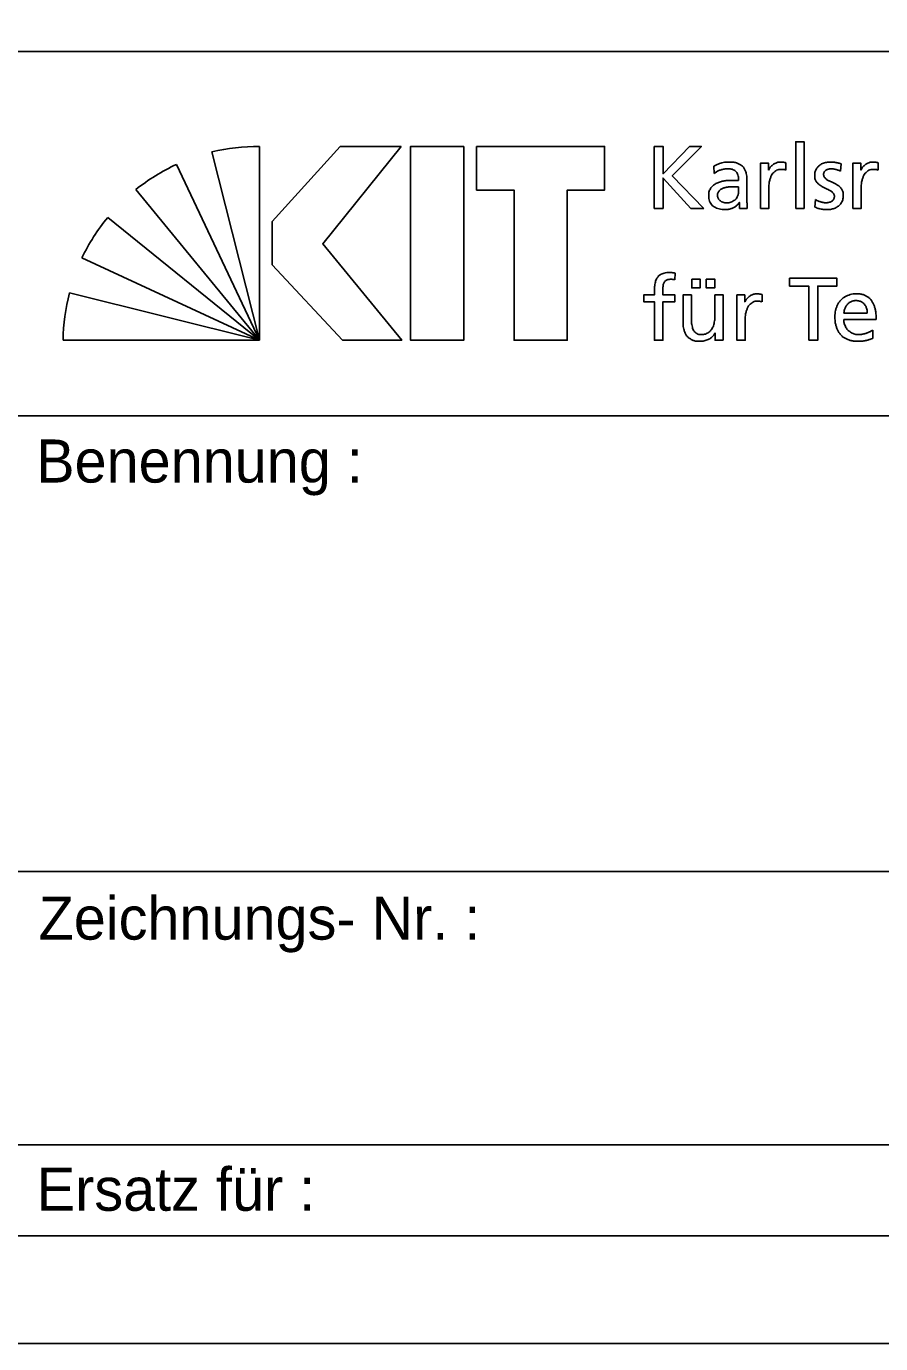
# Model space of a CAD drawing. Extents: x 0 to 11.9, y 0 to 8.4.
# Drawn here: x 11.007 to 11.403, y 0 to 0.612 of the extents above; entities that cross this region are included whole.
import ezdxf

# ---------------------------------------------------------------- set-up
doc = ezdxf.new("R2010")
doc.units = 0
doc.layers.add('90_Plankopf', color=7, linetype='Continuous')

msp = doc.modelspace()

# ---------------------------------------------------------------- linework, layer by layer
at = {"layer": '90_Plankopf'}
for p, q in [((10.0612, 0.5999), (11.84, 0.5999)), ((10.0612, 0.5999), (11.84, 0.5999)), ((11.09275, 0.55333), (11.11481, 0.46586)), ((11.11481, 0.46586), (11.11481, 0.55584)), ((11.2981, 0.55586), (11.2981, 0.52706)), ((11.11481, 0.46586), (11.07633, 0.54752)), ((11.32579, 0.54662), (11.326, 0.54332)), ((11.35926, 0.54484), (11.35926, 0.54831)), ((11.38457, 0.54439), (11.3849, 0.54778)), ((11.40211, 0.54484), (11.40211, 0.54831)), ((11.34118, 0.53118), (11.34118, 0.53989)), ((11.05744, 0.53585), (11.11481, 0.46586)), ((11.3373, 0.53709), (11.3373, 0.53523)), ((11.2981, 0.52706), (11.30222, 0.52706)), ((11.31506, 0.52706), (11.32108, 0.52706)), ((11.37297, 0.53118), (11.37277, 0.52772)), ((11.11481, 0.46586), (11.04434, 0.52286)), ((11.0324, 0.50413), (11.11481, 0.46586)), ((11.30773, 0.49393), (11.3079, 0.49706)), ((11.11481, 0.46586), (11.02658, 0.48788)), ((11.34827, 0.48365), (11.34827, 0.48712)), ((11.39706, 0.47841), (11.38616, 0.47841)), ((11.38616, 0.47552), (11.40119, 0.47552)), ((11.02364, 0.46586), (11.11481, 0.46586)), ((11.39958, 0.46673), (11.39958, 0.47061)), ((11.00001, 0.4307), (11.84, 0.4307)), ((11.00001, 0.2192), (11.84, 0.2192)), ((11.00001, 0.0923), (11.84, 0.0923)), ((11.84, 0.05), (10.0612, 0.05)), ((10.178, 0.05), (11.84, 0.05)), ((10.178, 0.05), (11.84, 0.05))]:
    msp.add_line(p, q, dxfattribs=at)
for points in [[(0, 0), (11.89, 0), (11.89, 8.41), (0, 8.41)], [(0.25, 0.05), (11.84, 0.05), (11.84, 8.36), (0.25, 8.36)], [(11.18066, 0.55586), (11.15236, 0.55586), (11.12073, 0.52099), (11.12073, 0.50092), (11.15338, 0.46586), (11.18085, 0.46586), (11.14422, 0.51063)], [(11.2097, 0.55586), (11.2097, 0.46586), (11.18501, 0.46586), (11.18501, 0.55586)], [(11.21562, 0.55586), (11.21562, 0.5356), (11.23301, 0.5356), (11.23301, 0.46586), (11.25771, 0.46586), (11.25771, 0.5356), (11.2751, 0.5356), (11.2751, 0.55586)]]:
    msp.add_lwpolyline(points, close=True, dxfattribs=at)
for points in [[(11.36381, 0.52706), (11.36768, 0.52706), (11.36768, 0.55801), (11.36381, 0.55801), (11.36381, 0.52706)], [(11.32108, 0.52706), (11.30647, 0.54224), (11.32001, 0.55586), (11.31452, 0.55586), (11.30222, 0.54319), (11.30222, 0.55586), (11.2981, 0.55586)], [(11.35122, 0.54484), (11.35113, 0.54484), (11.35113, 0.5481), (11.3475, 0.5481), (11.3475, 0.52706), (11.35138, 0.52706), (11.35138, 0.53663)], [(11.39407, 0.54484), (11.39398, 0.54484), (11.39398, 0.5481), (11.39035, 0.5481), (11.39035, 0.52706), (11.39423, 0.52706), (11.39423, 0.53663)], [(11.30222, 0.52706), (11.30222, 0.54117), (11.31506, 0.52706)], [(11.33763, 0.52978), (11.33772, 0.52978), (11.33772, 0.52706), (11.34135, 0.52706)], [(11.31554, 0.49426), (11.31554, 0.49013), (11.31942, 0.49013), (11.31942, 0.49426), (11.31554, 0.49426)], [(11.32231, 0.49426), (11.32231, 0.49013), (11.32619, 0.49013), (11.32619, 0.49426), (11.32231, 0.49426)], [(11.3699, 0.46586), (11.37403, 0.46586), (11.37403, 0.49104), (11.38298, 0.49104), (11.38298, 0.49467), (11.36094, 0.49467), (11.36094, 0.49104), (11.3699, 0.49104), (11.3699, 0.46586)], [(11.29824, 0.48885), (11.29824, 0.48691), (11.29329, 0.48691), (11.29329, 0.48378), (11.29824, 0.48378), (11.29824, 0.46586), (11.30212, 0.46586), (11.30212, 0.48378), (11.30769, 0.48378), (11.30769, 0.48691), (11.30212, 0.48691), (11.30212, 0.48918)], [(11.31542, 0.47602), (11.31542, 0.48691), (11.31154, 0.48691), (11.31154, 0.47441)], [(11.33015, 0.46586), (11.33015, 0.48691), (11.32627, 0.48691), (11.32627, 0.47717)], [(11.34022, 0.48365), (11.34014, 0.48365), (11.34014, 0.48691), (11.33651, 0.48691), (11.33651, 0.46586), (11.34039, 0.46586), (11.34039, 0.47544)], [(11.32631, 0.46921), (11.32639, 0.46921), (11.32639, 0.46586), (11.33015, 0.46586)]]:
    msp.add_lwpolyline(points, dxfattribs=at)
for centre, start, end in [((11.11449, 0.46056), 89.80527, 103.18947), ((11.11662, 0.46118), 115.01261, 128.3968), ((11.11816, 0.46263), 140.78977, 154.17397), ((11.11891, 0.46438), 165.72225, 179.10644)]:
    msp.add_arc(centre, 0.09528, start, end, dxfattribs=at)
for points in [[(11.34118, 0.53989), (11.34119, 0.5418), (11.34091, 0.54341), (11.34033, 0.5447), (11.33975, 0.54599), (11.33884, 0.54696), (11.33759, 0.54762), (11.33635, 0.54827), (11.33472, 0.5486), (11.33272, 0.5486), (11.33138, 0.54859), (11.33014, 0.54841), (11.32898, 0.54804), (11.32782, 0.54768), (11.32676, 0.54721), (11.32579, 0.54662)], [(11.326, 0.54332), (11.32653, 0.54376), (11.32713, 0.54414), (11.32779, 0.54446), (11.32846, 0.54478), (11.32916, 0.54503), (11.3299, 0.5452), (11.33063, 0.54538), (11.33137, 0.54546), (11.3321, 0.54546), (11.33339, 0.54546), (11.33441, 0.54526), (11.33518, 0.54485), (11.33594, 0.54444), (11.33649, 0.54383), (11.33682, 0.54302), (11.33715, 0.54219), (11.33731, 0.54118), (11.3373, 0.53997)], [(11.35926, 0.54831), (11.35899, 0.54837), (11.35873, 0.54841), (11.35849, 0.54846), (11.35824, 0.5485), (11.35798, 0.54854), (11.35769, 0.54856), (11.35741, 0.54859), (11.35708, 0.5486), (11.3567, 0.5486), (11.35595, 0.54859), (11.35523, 0.54843), (11.35452, 0.54811), (11.35382, 0.54779), (11.35318, 0.54736), (11.35261, 0.54679), (11.35203, 0.54623), (11.35157, 0.54558), (11.35122, 0.54484)], [(11.35138, 0.53663), (11.35139, 0.5384), (11.35163, 0.53993), (11.3521, 0.54121), (11.35257, 0.54249), (11.35323, 0.54348), (11.35409, 0.54416), (11.35494, 0.54486), (11.35595, 0.54521), (11.35712, 0.54521), (11.35746, 0.54522), (11.3578, 0.54519), (11.35818, 0.54514), (11.35855, 0.54509), (11.35891, 0.54499), (11.35926, 0.54484)], [(11.3849, 0.54778), (11.38414, 0.54801), (11.38337, 0.5482), (11.38259, 0.54836), (11.38181, 0.54851), (11.38097, 0.54859), (11.38007, 0.5486), (11.37903, 0.5486), (11.37805, 0.54847), (11.37716, 0.5482), (11.37625, 0.54794), (11.37547, 0.54753), (11.3748, 0.547), (11.37412, 0.54647), (11.37359, 0.54579), (11.37322, 0.54498), (11.37284, 0.54417), (11.37265, 0.54321), (11.37264, 0.54212), (11.37265, 0.54128), (11.37282, 0.54056), (11.37315, 0.53994), (11.37347, 0.53933), (11.37391, 0.5388), (11.37445, 0.53834), (11.375, 0.5379), (11.37559, 0.5375), (11.37623, 0.53715), (11.37688, 0.5368), (11.37753, 0.53647), (11.37817, 0.53617), (11.37882, 0.53586), (11.37942, 0.53555), (11.37995, 0.53522), (11.3805, 0.5349), (11.38093, 0.53454), (11.38126, 0.53413), (11.38158, 0.53373), (11.38176, 0.53325), (11.38176, 0.53271), (11.38176, 0.53215), (11.38163, 0.53167), (11.38139, 0.53128), (11.38116, 0.5309), (11.38084, 0.53059), (11.38045, 0.53035), (11.38006, 0.53012), (11.37963, 0.52995), (11.37917, 0.52985), (11.37871, 0.52975), (11.37825, 0.5297), (11.3778, 0.5297), (11.37742, 0.5297), (11.37695, 0.52975), (11.37639, 0.52986), (11.37584, 0.52997), (11.37526, 0.53014), (11.37466, 0.53036), (11.37405, 0.53058), (11.3735, 0.53085), (11.37297, 0.53118)], [(11.37277, 0.52772), (11.37366, 0.52726), (11.3746, 0.52694), (11.37558, 0.52678), (11.37656, 0.52662), (11.37755, 0.52655), (11.37854, 0.52656), (11.37949, 0.52656), (11.3804, 0.52669), (11.38127, 0.52695), (11.38215, 0.52722), (11.38293, 0.52762), (11.38363, 0.52816), (11.38431, 0.52869), (11.38487, 0.52938), (11.38527, 0.5302), (11.38568, 0.53103), (11.38588, 0.532), (11.38589, 0.53312), (11.38588, 0.53408), (11.38571, 0.53489), (11.38539, 0.53556), (11.38506, 0.53622), (11.38462, 0.53679), (11.38408, 0.53726), (11.38354, 0.53772), (11.38295, 0.53811), (11.3823, 0.53845), (11.38165, 0.53878), (11.38101, 0.53909), (11.38036, 0.53937), (11.37971, 0.53966), (11.37912, 0.53995), (11.37858, 0.54026), (11.37804, 0.54058), (11.3776, 0.54095), (11.37727, 0.54136), (11.37695, 0.54179), (11.37678, 0.5423), (11.37677, 0.54291), (11.37678, 0.54348), (11.37696, 0.54396), (11.37729, 0.54434), (11.37763, 0.54472), (11.37808, 0.545), (11.37864, 0.54519), (11.3792, 0.54538), (11.37982, 0.54546), (11.38048, 0.54546), (11.38072, 0.54546), (11.38102, 0.54543), (11.38139, 0.54538), (11.38175, 0.54531), (11.38213, 0.54523), (11.38254, 0.54513), (11.38295, 0.54503), (11.38333, 0.54491), (11.38369, 0.54478), (11.38405, 0.54466), (11.38434, 0.54453), (11.38457, 0.54439)], [(11.40211, 0.54831), (11.40184, 0.54837), (11.40158, 0.54841), (11.40134, 0.54846), (11.4011, 0.5485), (11.40083, 0.54854), (11.40054, 0.54856), (11.40026, 0.54859), (11.39993, 0.5486), (11.39955, 0.5486), (11.3988, 0.54859), (11.39808, 0.54843), (11.39737, 0.54811), (11.39667, 0.54779), (11.39603, 0.54736), (11.39546, 0.54679), (11.39488, 0.54623), (11.39442, 0.54558), (11.39407, 0.54484)], [(11.39423, 0.53663), (11.39424, 0.5384), (11.39448, 0.53993), (11.39495, 0.54121), (11.39542, 0.54249), (11.39608, 0.54348), (11.39694, 0.54416), (11.39779, 0.54486), (11.3988, 0.54521), (11.39997, 0.54521), (11.4003, 0.54522), (11.40065, 0.54519), (11.40103, 0.54514), (11.4014, 0.54509), (11.40175, 0.54499), (11.40211, 0.54484)], [(11.3373, 0.53997), (11.3368, 0.54), (11.33633, 0.54002), (11.33589, 0.54003), (11.33546, 0.54004), (11.33502, 0.54005), (11.33459, 0.54006), (11.33415, 0.54006), (11.33368, 0.54006), (11.33318, 0.54006), (11.33237, 0.54006), (11.33151, 0.53999), (11.33063, 0.53984), (11.32973, 0.5397), (11.32886, 0.53947), (11.32801, 0.53914), (11.32715, 0.53881), (11.32638, 0.53838), (11.32569, 0.53785), (11.32499, 0.53731), (11.32444, 0.53665), (11.32403, 0.53588), (11.32362, 0.53509), (11.32341, 0.53418), (11.3234, 0.53312), (11.32341, 0.5316), (11.32374, 0.53035), (11.32439, 0.52939), (11.32504, 0.52842), (11.32594, 0.5277), (11.3271, 0.52724), (11.32825, 0.52679), (11.32959, 0.52656), (11.33111, 0.52656), (11.332, 0.52657), (11.3328, 0.52668), (11.3335, 0.52689), (11.33421, 0.52709), (11.33483, 0.52736), (11.33536, 0.52769), (11.3359, 0.52802), (11.33635, 0.52837), (11.33673, 0.52874), (11.3371, 0.52911), (11.33741, 0.52945), (11.33763, 0.52978)], [(11.3373, 0.53523), (11.3373, 0.53418), (11.33708, 0.53323), (11.33664, 0.5324), (11.3362, 0.53157), (11.33554, 0.53092), (11.33467, 0.53043), (11.3338, 0.52995), (11.33272, 0.5297), (11.33144, 0.5297), (11.331, 0.5297), (11.33054, 0.52978), (11.33008, 0.52992), (11.32963, 0.53007), (11.3292, 0.53028), (11.32882, 0.53057), (11.32843, 0.53087), (11.32812, 0.53123), (11.32789, 0.53165), (11.32765, 0.53207), (11.32753, 0.53257), (11.32752, 0.53312), (11.32754, 0.53386), (11.32772, 0.53448), (11.32808, 0.53497), (11.32844, 0.53546), (11.32891, 0.53586), (11.32949, 0.53615), (11.33007, 0.53645), (11.33069, 0.53667), (11.33135, 0.53682), (11.33201, 0.53696), (11.33265, 0.53706), (11.33326, 0.53711), (11.33387, 0.53715), (11.33439, 0.53717), (11.33483, 0.53717), (11.33524, 0.53717), (11.33565, 0.53715), (11.33607, 0.53713), (11.33648, 0.53711), (11.33689, 0.53709), (11.3373, 0.53709)], [(11.34135, 0.52706), (11.34132, 0.52726), (11.34129, 0.52753), (11.34126, 0.52787), (11.34125, 0.52821), (11.34122, 0.52865), (11.34121, 0.52919), (11.34119, 0.52973), (11.34118, 0.53039), (11.34118, 0.53118)], [(11.3079, 0.49706), (11.30751, 0.49712), (11.3071, 0.49719), (11.30668, 0.49723), (11.30625, 0.49728), (11.30579, 0.49731), (11.3053, 0.49731), (11.30388, 0.4973), (11.3027, 0.4971), (11.30178, 0.49671), (11.30086, 0.49631), (11.30014, 0.49574), (11.29962, 0.495), (11.2991, 0.49426), (11.29875, 0.49337), (11.29854, 0.49233), (11.29833, 0.49129), (11.29824, 0.49014), (11.29824, 0.48885)], [(11.30212, 0.48918), (11.30212, 0.4899), (11.30216, 0.49056), (11.30224, 0.49116), (11.30232, 0.49177), (11.30249, 0.4923), (11.30275, 0.49275), (11.303, 0.4932), (11.30338, 0.49355), (11.30388, 0.49379), (11.30439, 0.49404), (11.30505, 0.49417), (11.30588, 0.49417), (11.30621, 0.49417), (11.30655, 0.49415), (11.30688, 0.49411), (11.30722, 0.49407), (11.3075, 0.49401), (11.30773, 0.49393)], [(11.34827, 0.48712), (11.348, 0.48717), (11.34774, 0.48722), (11.3475, 0.48727), (11.34725, 0.48731), (11.34698, 0.48734), (11.3467, 0.48737), (11.34642, 0.48739), (11.34609, 0.4874), (11.34571, 0.4874), (11.34496, 0.4874), (11.34423, 0.48724), (11.34352, 0.48692), (11.34282, 0.4866), (11.34218, 0.48616), (11.34161, 0.4856), (11.34104, 0.48503), (11.34057, 0.48439), (11.34022, 0.48365)], [(11.34039, 0.47544), (11.34039, 0.47721), (11.34064, 0.47873), (11.3411, 0.48001), (11.34158, 0.48129), (11.34224, 0.48228), (11.3431, 0.48297), (11.34395, 0.48367), (11.34496, 0.48401), (11.34612, 0.48402), (11.34646, 0.48403), (11.34681, 0.484), (11.34718, 0.48395), (11.34756, 0.48389), (11.34791, 0.48379), (11.34827, 0.48365)], [(11.40119, 0.47552), (11.40119, 0.47722), (11.40103, 0.4788), (11.40072, 0.48023), (11.40041, 0.48168), (11.39989, 0.48293), (11.39918, 0.484), (11.39846, 0.48507), (11.39751, 0.48591), (11.39631, 0.4865), (11.39512, 0.48709), (11.39365, 0.4874), (11.3919, 0.4874), (11.39041, 0.4874), (11.38906, 0.48714), (11.38785, 0.48662), (11.38665, 0.4861), (11.38561, 0.48537), (11.38474, 0.48442), (11.38387, 0.48347), (11.38321, 0.48235), (11.38275, 0.48105), (11.38228, 0.47976), (11.38205, 0.47833), (11.38204, 0.47676), (11.38204, 0.47504), (11.38225, 0.47348), (11.38269, 0.47209), (11.38312, 0.47069), (11.38379, 0.4695), (11.38469, 0.4685), (11.38558, 0.46749), (11.38671, 0.46672), (11.38808, 0.46619), (11.38945, 0.46564), (11.39107, 0.46538), (11.39293, 0.46537), (11.39408, 0.46538), (11.39506, 0.46545), (11.39587, 0.4656), (11.39667, 0.46575), (11.39737, 0.46593), (11.39797, 0.46614), (11.39855, 0.46634), (11.39909, 0.46654), (11.39958, 0.46673)], [(11.38616, 0.47841), (11.38623, 0.4791), (11.38639, 0.47978), (11.38664, 0.48047), (11.38688, 0.48116), (11.38722, 0.48179), (11.38768, 0.48236), (11.38812, 0.48294), (11.38869, 0.48339), (11.38937, 0.48374), (11.39006, 0.48408), (11.39087, 0.48426), (11.39182, 0.48427), (11.39266, 0.48426), (11.3934, 0.48411), (11.39404, 0.48381), (11.3947, 0.4835), (11.39524, 0.48309), (11.39569, 0.48255), (11.39614, 0.48201), (11.39648, 0.48139), (11.39671, 0.48069), (11.39694, 0.47998), (11.39706, 0.47922), (11.39706, 0.47841)], [(11.32627, 0.47717), (11.32627, 0.47589), (11.32615, 0.47471), (11.32589, 0.47365), (11.32564, 0.4726), (11.32525, 0.47169), (11.32473, 0.47092), (11.32421, 0.47015), (11.32354, 0.46956), (11.32273, 0.46914), (11.32193, 0.46872), (11.32097, 0.46851), (11.31987, 0.4685), (11.31875, 0.46857), (11.31786, 0.46889), (11.31721, 0.46945), (11.31656, 0.47002), (11.3161, 0.47084), (11.31582, 0.47193), (11.31554, 0.47302), (11.31541, 0.47438), (11.31542, 0.47602)], [(11.31154, 0.47441), (11.31154, 0.47251), (11.31181, 0.4709), (11.31237, 0.46955), (11.31293, 0.4682), (11.31379, 0.46717), (11.31496, 0.46645), (11.31612, 0.46574), (11.31761, 0.46538), (11.31942, 0.46537), (11.3204, 0.46538), (11.32135, 0.46553), (11.32225, 0.46583), (11.32315, 0.46614), (11.32396, 0.46658), (11.32466, 0.46715), (11.32537, 0.46772), (11.32592, 0.46841), (11.32631, 0.46921)], [(11.39958, 0.47061), (11.39933, 0.47041), (11.39899, 0.47019), (11.39852, 0.46995), (11.39806, 0.46971), (11.39754, 0.46948), (11.39694, 0.46926), (11.39634, 0.46904), (11.39572, 0.46886), (11.39506, 0.46872), (11.3944, 0.46858), (11.39374, 0.46851), (11.39309, 0.4685), (11.39217, 0.46851), (11.3913, 0.46868), (11.39046, 0.46902), (11.38964, 0.46935), (11.38889, 0.46983), (11.38825, 0.47045), (11.38761, 0.47107), (11.3871, 0.47181), (11.38673, 0.47267), (11.38636, 0.47353), (11.38617, 0.47448), (11.38616, 0.47552)]]:
    msp.add_open_spline(points, degree=3, dxfattribs=at)

# ---------------------------------------------------------------- texts
for s, p in [('Benennung :', (11.01113, 0.39979)), ('Zeichnungs- Nr. :', (11.01227, 0.18758)), ('Ersatz für :', (11.01139, 0.06169))]:
    msp.add_text(s, height=0.02, dxfattribs=at).set_placement(p)

doc.saveas('drawing.dxf')
